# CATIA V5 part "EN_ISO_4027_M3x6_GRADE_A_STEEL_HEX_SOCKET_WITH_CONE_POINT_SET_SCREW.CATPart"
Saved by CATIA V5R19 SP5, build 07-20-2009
Part number: EN ISO 4027 SCREW M3x6 GRADE A STEEL HEX SOCKET SET WITH CONE POINT
Publications: "Mating Face", "Axis"
Bounding box of the stored display mesh (mm): x -6 to 0, y -1.5 to 1.5, z -1.5 to 1.5
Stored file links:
  Z:\UA\ATLAS\atlascar\ServoPiloto\dir\suportePotenciometro\V2\potenciometro\EN_ISO_4027_M3x6_GRADE_A_STEEL_HEX_SOCKET_WITH_CONE_POINT_SET_SCREW.CATPart
  Z:\programs_vbox\Dassault Systemes\B19\intel_a\startup\components\MechanicalStandardParts\ISO_Standards\Design_Tables\ISO_4027_GRADE_A_HEXAGON_SOCKET_SET_SCREW_CONE_POINT.txt
  Z:\programs_vbox\Dassault Systemes\B19\intel_a\startup\components\MechanicalStandardParts\EN_Standards\Design_Tables\EN_ISO_4027_GRADE_A_HEXAGON_SOCKET_SET_SCREW_CONE_POINT.txt
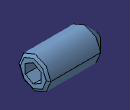
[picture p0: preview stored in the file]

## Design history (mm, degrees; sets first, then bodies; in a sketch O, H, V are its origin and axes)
Parameters
  Designation = "M3"
  l_nom_length = 6 mm
  p_pitch = 0.5 mm
  dt_dia_point = 1.5 mm
  d_dia = 3 mm
  s_across_flat = 1.5 mm
  t_depth_socket = 2 mm
  threading = 5.844 mm
  d1_dia_point = 0.75 mm
Body1 "PartBody" (main body)
  Sketch1 on yz-plane, origin (0, 0, 0), H (0, 1, 0), V (0, 0, 1)
    circle A1 centre (0, 0) radius 1.5
    radius A1 = 1.5 {= d_dia /2}
  Pad1: profile Sketch1, direction (-1, 0, 0), length 6 {= l_nom_length}
  Chamfer1: length 0.27 {= p_pitch *.54}, angle 30, on edge [face of Pad1 | face of Pad1]
  Chamfer2: length 1.125 {= (d_dia -d1_dia_point  )/2}, angle 45, on edge [face of Pad1 | face of Pad1]
  Body2
    Sketch2 on zx-plane, origin (0, 0, 0), H (-1, 0, 0), V (0, 0, 1)
      line L1 (0, 0) -> (0, 6.9282)
      line L2 (0, 6.9282) -> (15, 6.9282)
      point P2 (15, 6.9282)
      line L3 (15, 6.9282) -> (19, 0)
      point P3 (19, 0)
      axis line L4 (-8.7043, 0) -> (26.0294, 0)
      angle L3 L4 = 60
      distance P2 L1 = 15
      vertical: L1 V
      horizontal: L2 H, L4 H
      fix: L4
      coincidence: P3 L4
    Shaft1: profile Sketch2, axis Sketch2.L4, angle 360
    Body3
      Sketch3 on face of Pad1, origin (0, 0, 0), H (0, 1, 0), V (0, 0, 1)
        point P1 (0.75, -0.433)
        point P2 (0.75, 0.433)
        point P3 (0, 0.866)
        point P4 (-0.75, 0.433)
        point P5 (-0.75, -0.433)
        point P6 (0, -0.866)
        point P7 (0.75, 0)
        line L1 (0.75, -0.433) -> (0.75, 0.433)
        line L2 (0.75, 0.433) -> (0, 0.866)
        line L3 (0, 0.866) -> (-0.75, 0.433)
        line L4 (-0.75, 0.433) -> (-0.75, -0.433)
        line L5 (-0.75, -0.433) -> (0, -0.866)
        line L6 (0, -0.866) -> (0.75, -0.433)
        construction line L7 (0, 0) -> (0.75, 0)
        construction circle A1 centre (0, 0) radius 0.866
        construction arc A2 centre (-0.75, -0.433) radius 0.866 from (-0.75, 0.433) to (0, -0.866) cw
        construction arc A3 centre (0.75, 0.433) radius 0.866 from (0, 0.866) to (0.75, -0.433) ccw
        point P8 (-0.75, -0.433)
        point P9 (0.75, 0.433)
        distance L4 L1 = 1.5 {= s_across_flat}
        horizontal: L7 H
        coincidence: A1 P1, A1 P2, A1 P3, A1 P4, A1 P5, A1 P6, A2 P4, A2 P6, A2 O, P8 P5, A3 P3, A3 P1, A3 O, P9 P2
        midpoint: P7 L1
      Pad2: profile Sketch3, direction (-1, 0, 0), length 3 {= t_depth_socket *1.5}
    Intersect1: tool Body3
  Remove1: tool Body2
  Thread1: diameter 3 {= d_dia}, depth 5.844 {= threading}, pitch 1, on face of Pad1, from face of Pad1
